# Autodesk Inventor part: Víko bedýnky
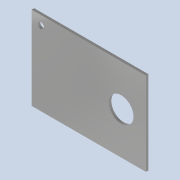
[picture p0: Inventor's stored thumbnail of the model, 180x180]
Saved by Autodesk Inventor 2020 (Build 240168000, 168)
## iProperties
Created: 2025-03
Part Number: Víko bedýnky
Material: Polypropylen
Document SubType Name: Modeling
Designer: doma
Density: 0.899 g/cm^3
Appearance: Hladká – středně šedá
Author: doma
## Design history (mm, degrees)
sketch "Náčrt1"
  geometry: L1 (-185, -135)-(185, -135); L2 (185, -135)-(185, 135); L3 (185, 135)-(-185, 135); L4 (-185, 135)-(-185, -135); L5 (-185, -135)-(185, 135); L6 (185, -135)-(-185, 135); 1 further point
  constraints: 12 end point, 2 midpoint, 2 parallel, 1 horizontal, 1 perpendicular
  dimensions: "d0" = 370 distance of L3.end L2.end; "d1" = 270 distance of L2.end L1.end
extrude "Vysunutí1" new body sketch "Náčrt1" distance "d2" = 8; taper "d3" = 0 deg
sketch "Náčrt2"
  geometry: L1 (-185, -135)-(-185, 135) reference; L2 (185, 135)-(185, -135) reference; L3 (-185, 135)-(185, 135) reference; C1 r 40 at (-105, 0); C2 r 10 at (155, 105); 1 further point
  constraints: 2 centre point
  dimensions: "d4" = 80 diameter of C1; "d5" = 80 distance from line of L1 C1.centre; "d8" = 20 diameter of C2; "d9" = 30 distance from line of L2 C2.centre; "d10" = 30 distance from line of L3 C2.centre
extrude "Vysunutí2" cut sketch "Náčrt2" distance "d6" = 8; taper "d7" = 0 deg
node "Těleso1"
